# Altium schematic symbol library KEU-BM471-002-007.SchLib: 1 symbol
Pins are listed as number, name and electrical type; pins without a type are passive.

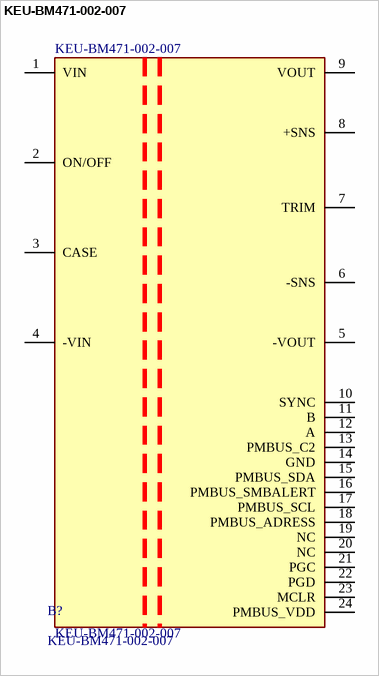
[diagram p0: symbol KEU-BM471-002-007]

## KEU-BM471-002-007
designator B?
9-70Vin XXVout XXXW Isolated Half Brick with Flanged Option; MFG: KOLT
footprint KEU-BM471-002-007 (Footprint not found)
pins: 1 VIN, 2 ON/OFF, 3 CASE, 4 -VIN, 5 -VOUT, 6 -SNS, 7 TRIM, 8 +SNS, 9 VOUT, 10 SYNC, 11 B, 12 A, 13 PMBUS_C2, 14 GND, 15 PMBUS_SDA, 16 PMBUS_SMBALERT, 17 PMBUS_SCL, 18 PMBUS_ADRESS, 19 NC, 20 NC, 21 PGC, 22 PGD, 23 MCLR, 24 PMBUS_VDD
